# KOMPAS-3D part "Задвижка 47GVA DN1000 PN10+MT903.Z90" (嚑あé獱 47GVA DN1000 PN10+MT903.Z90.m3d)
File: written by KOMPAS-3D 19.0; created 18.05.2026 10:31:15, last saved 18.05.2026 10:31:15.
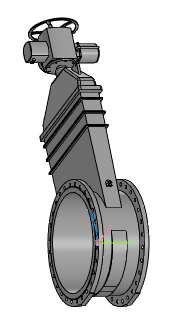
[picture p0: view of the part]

Document properties: Автор: Энергия; Полное имя файла: ..\Задвижка 47GVA DN40_DN1000+MT903.Z\Задвижка 47GVA DN1000 PN10+MT903.Z90.a3d

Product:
- Part/product: Задвижка 47GVA DN1000 PN10+MT903.Z90
    Масса: 2947.89
  - Body: Электропривод MT903.Z90-120
      Масса: 369.82
  - Body: Задвижка 47GVA DN1000 PN10_F25 без исполнительного механизма
      Масса: 2578.07

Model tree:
1. Операция без истории:1
2. Операция без истории:2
